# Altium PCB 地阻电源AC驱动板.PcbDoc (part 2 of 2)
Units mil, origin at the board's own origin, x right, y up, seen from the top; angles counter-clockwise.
Board outline 3149.61 x 5118.11 mil, 2 copper layers (Top Layer, Bottom Layer); 154 components, 62 nets, 426 pads, 73 vias.
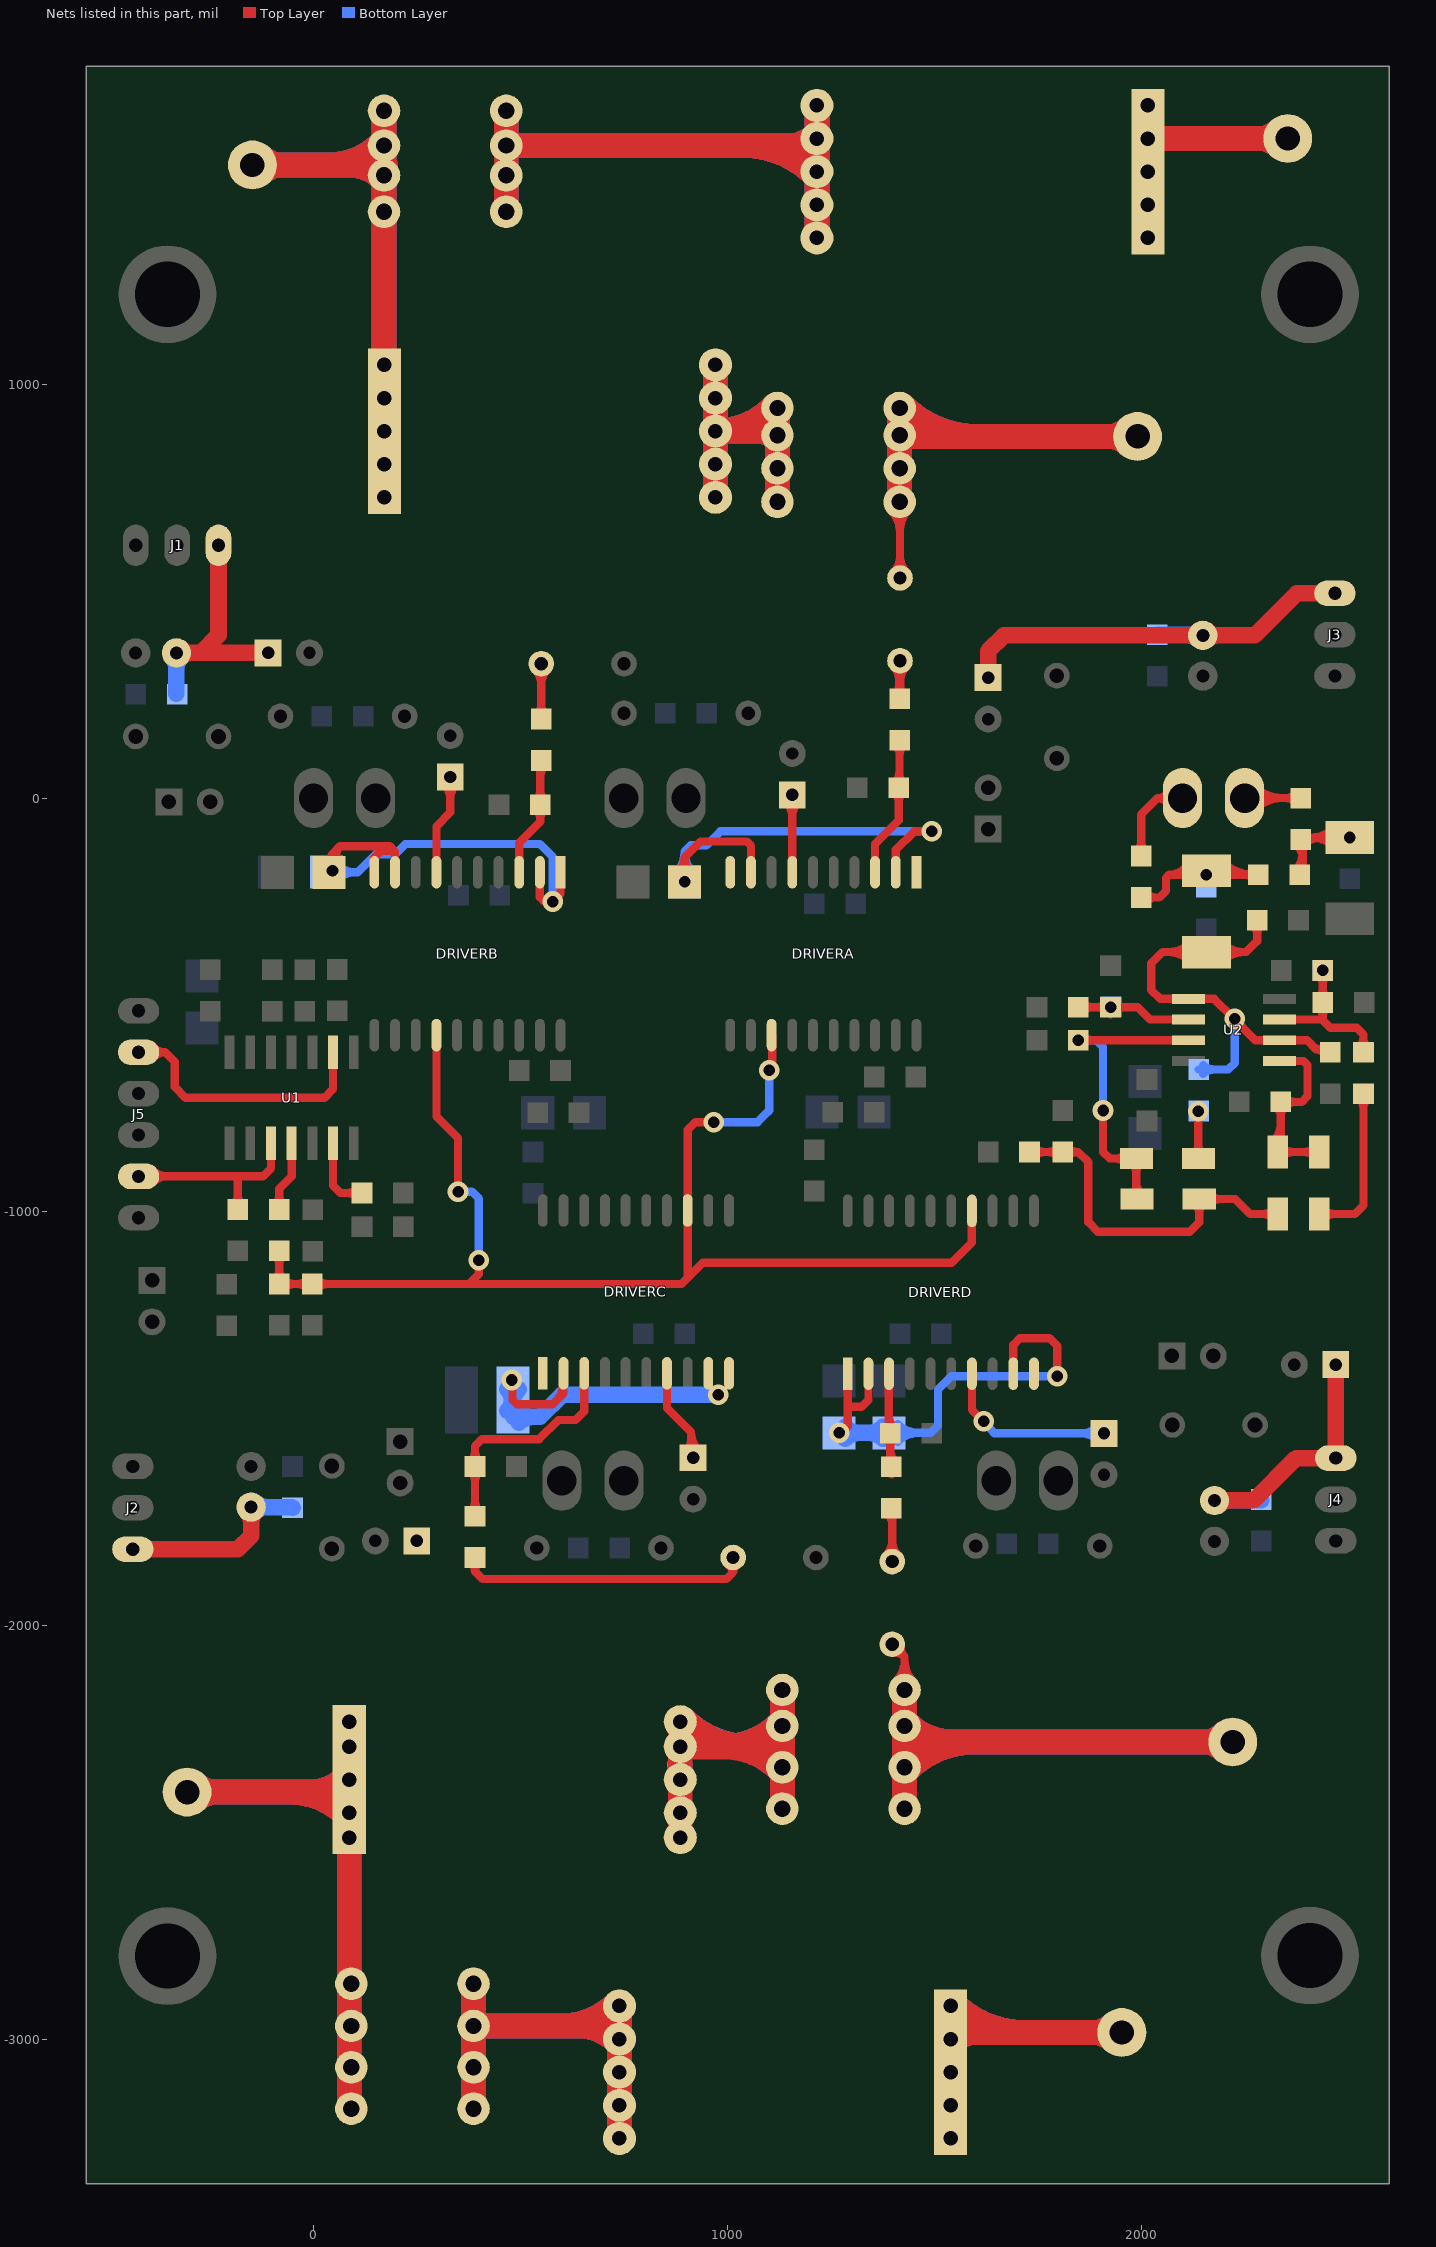
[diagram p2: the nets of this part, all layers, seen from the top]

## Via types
v1: diameter 50, hole 28, Top Layer to Bottom Layer, 54 vias
v2: diameter 50, hole 27.99, Top Layer to Bottom Layer, 19 vias

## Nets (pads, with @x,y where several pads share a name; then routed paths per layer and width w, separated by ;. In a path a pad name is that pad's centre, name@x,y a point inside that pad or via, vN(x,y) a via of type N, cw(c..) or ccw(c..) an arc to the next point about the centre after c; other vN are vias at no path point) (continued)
IPM2: J5.2 R50.1 U1.3 | length 565
  Top Layer w20: J5.2@-389.06,-929.02 cw(c-353.21,-964.87) -353.21,-914.17 cw(c-353.21,-863.47) J5.2@-389.06,-899.32 ; J5.2@-382.91,-914.17 -122.28,-914.17 -102.91,-894.8 U1.3@-102.91,-834.17 ; R50.1@-193.52,-983.57 ccw(c-219.13,-957.96) -182.91,-957.96 ccw(c-146.7,-957.96) R50.1@-172.31,-983.57 ; R50.1@-182.91,-994.17 -182.91,-914.36
IPM2*: C47.1 DRIVERA.13 DRIVERB.14 DRIVERC.13 DRIVERD.14 R52.2 R56.2 | length 3584.5
  Top Layer w20: C47.1@-93.52,-1163.57 ccw(c-119.13,-1137.96) -82.91,-1137.96 ccw(c-46.7,-1137.96) -72.31,-1163.57 ccw(c-46.7,-1137.96) -46.7,-1174.17 ccw(c-46.7,-1210.39) C47.1@-72.31,-1184.78 ; R52.2@-93.52,-1104.78 cw(c-119.13,-1130.39) -82.91,-1130.39 cw(c-46.7,-1130.39) R52.2@-72.31,-1104.78 ; R52.2@-82.91,-1094.17 C47.1@-82.91,-1174.17 R56.2@-2.91,-1174.17 889.26,-1174.17 904.09,-1159.35 ; R56.2@-13.52,-1184.78 ccw(c-39.13,-1210.39) -39.13,-1174.17 ccw(c-39.13,-1137.96) R56.2@-13.52,-1163.57 ; R56.2@7.69,-1184.78 cw(c33.3,-1210.39) 33.3,-1174.17 cw(c33.3,-1137.96) R56.2@7.69,-1163.57 ; DRIVERB.14@296.94,-572.85 296.94,-769.67 349.28,-822.01 v2(349.28,-951.13) ; 375.28,-1174.01 399.28,-1150.01 v1(399.28,-1117.2) ; 940.28,-1123.16 904.09,-1159.35 ; 940.28,-1123.11 1541.72,-1123.11 1590.94,-1073.9 DRIVERD.14@1590.94,-997.46 ; v2(967.28,-783.16) 923.28,-783.16 904.09,-802.35 DRIVERC.13@904.09,-996.47 904.09,-1159.35 ; v2(1101.28,-658.01) 1108.28,-651.01 DRIVERA.13@1108.28,-574.2
  Bottom Layer w20: v2(349.28,-951.13) 382.4,-951.13 399.28,-968.01 v1(399.28,-1117.2) ; v2(967.28,-783.16) 1073.13,-783.16 1099.78,-756.51 ; 1101.28,-755.01 v2(1101.28,-658.01)
NetC1_2: C1.2 C2.2 C3.2 C4.2 R3.2 R4.2 R5.2 R6.2 R7.2 | length 2451.3
  Top Layer w60: C4.2@386.55,-3167.16 C3.2@386.55,-3067.16 C1.2@386.55,-2967.16 ; C2.2@386.55,-2865.16 C1.2@386.55,-2967.16 ; 598.89,-2967.16 ccw(c598.89,-2778.62) R5.2@732.2,-2911.94 ; 638.24,-2967.16 cw(c638.24,-3100.04) R4.2@732.2,-3006.08 ; R4.2@737.43,-2967.16 C1.2@386.55,-2967.16 ; R6.2@739.28,-3239.01 R3.2@739.28,-3159.01 R7.2@739.28,-3079.01 R4.2@739.28,-2999.01 R5.2@739.28,-2919.01
  Bottom Layer w60: C4.2@386.55,-3167.16 C3.2@386.55,-3067.16 C1.2@386.55,-2967.16 ; C2.2@386.55,-2865.16 C1.2@386.55,-2967.16 ; 598.89,-2967.16 ccw(c598.89,-2778.62) R5.2@732.2,-2911.94 ; 638.24,-2967.16 cw(c638.24,-3100.04) R4.2@732.2,-3006.08 ; R4.2@738.13,-2967.16 C1.2@386.55,-2967.16 ; R6.2@739.28,-3239.01 R3.2@739.28,-3159.01 R7.2@739.28,-3079.01 R4.2@739.28,-2999.01 R5.2@739.28,-2919.01
NetC8_2: C8.2 C9.2 C10.2 C11.2 R15.2 R16.2 R17.2 R18.2 R19.2 | length 3114.5
  Top Layer w60: C11.2@465.55,1416.84 C10.2@465.55,1504.84 C9.2@465.55,1576.84 ; C8.2@465.55,1660.84 C9.2@465.55,1576.84 ; 1040.04,1576.84 cw(c1040.04,1337.61) R19.2@1209.2,1506.77 ; 1151.09,1576.84 ccw(c1151.09,1659.03) R18.2@1209.2,1600.91 ; R18.2@1213.43,1576.84 C9.2@465.55,1576.84 ; R17.2@1216.28,1353.84 R16.2@1216.28,1433.84 R19.2@1216.28,1513.84 R18.2@1216.28,1593.84 R15.2@1216.28,1673.84
  Bottom Layer w60: C11.2@465.55,1416.84 C10.2@465.55,1504.84 C9.2@465.55,1576.84 ; C8.2@465.55,1660.84 C9.2@465.55,1576.84 ; 1040.04,1576.84 cw(c1040.04,1337.61) R19.2@1209.2,1506.77 ; 1151.09,1576.84 ccw(c1151.09,1659.03) R18.2@1209.2,1600.91 ; R18.2@1199.28,1576.84 C9.2@465.55,1576.84 ; R17.2@1216.28,1353.84 R16.2@1216.28,1433.84 R19.2@1216.28,1513.84 R18.2@1216.28,1593.84 R15.2@1216.28,1673.84
NetC16_1: C16.1 DRIVERB.3 R13.2 | length 459.4
  Top Layer w20: DRIVERB.3@496.94,-179.15 496.94,-108.57 548.7,-56.81 ; C16.1@537.48,-26.78 cw(c511.87,-52.39) 548.09,-52.39 cw(c584.3,-52.39) C16.1@558.69,-26.78 ; C16.1@537.48,-5.57 ccw(c511.87,20.04) 548.09,20.04 ccw(c584.3,20.04) C16.1@558.69,-5.57 ; R13.2@539.67,80.39 cw(c519.35,60.06) 548.09,60.06 ; 548.09,-56.2 C16.1@548.09,-16.17 R13.2@548.09,88.8 ; 548.09,49.49 cw(c591.77,49.49) R13.2@560.88,80.39
NetC18_1: C18.1 DRIVERC.3 R14.2 | length 730.1
  Top Layer w20: R14.2@379.67,-1724.55 ccw(c354.06,-1698.94) 390.28,-1698.94 ccw(c426.49,-1698.94) R14.2@400.88,-1724.55 ; C18.1@379.67,-1625.76 cw(c354.06,-1651.37) 390.28,-1651.37 cw(c426.49,-1651.37) C18.1@400.88,-1625.76 ; C18.1@379.67,-1604.55 ccw(c354.06,-1578.94) 390.28,-1578.94 ccw(c426.49,-1578.94) C18.1@400.88,-1604.55 ; R14.2@390.28,-1735.16 C18.1@390.28,-1615.16 390.28,-1566.16 407.28,-1549.16 545.28,-1549.16 591.65,-1502.78 633.28,-1502.78 654.09,-1481.97 DRIVERC.3@654.09,-1390.17
NetC20_2: C20.2 C21.2 C22.2 C23.2 R23.2 R24.2 R25.2 R26.2 R27.2 | length 2309.2
  Top Layer w60: R24.2@886.28,-2512.01 R23.2@886.28,-2452.01 R27.2@886.28,-2372.01 R26.2@886.28,-2292.01 R25.2@886.28,-2232.01 ; R26.2@892.28,-2293.01 1133,-2293.01 ; R25.2@893.35,-2224.94 ccw(c1057.69,-2060.6) 1057.69,-2293.01 ; 987.62,-2293.01 ccw(c987.62,-2096.77) C21.2@1126.37,-2235.53 ; 991.72,-2293.01 cw(c991.72,-2483.44) C22.2@1126.37,-2348.78 ; C20.2@1133,-2442.16 C22.2@1133,-2342.16 1133,-2293.01 ; C23.2@1133,-2155.16 C21.2@1133,-2242.16 1133,-2293.01
  Bottom Layer w60: R27.2@884.28,-2337.01 R27.2@886.28,-2337.01 ; R26.2@890.28,-2292.01 1133,-2292.01 ; R25.2@893.35,-2224.94 ccw(c1055.27,-2063.01) 1055.27,-2292.01 ; 989.31,-2292.01 cw(c989.31,-2485.85) C22.2@1126.37,-2348.78 ; 990.03,-2292.01 ccw(c990.03,-2099.19) C21.2@1126.37,-2235.53 ; C20.2@1133,-2442.16 C22.2@1133,-2342.16 1133,-2292.01 ; C23.2@1133,-2155.16 C21.2@1133,-2242.16 1133,-2292.01
NetC26_2: C26.2 C27.2 C28.2 C29.2 R34.2 R35.2 R36.2 R37.2 R38.2 | length 1792.5
  Top Layer w60: R37.2@971.28,726.84 R36.2@971.28,806.84 R35.2@971.28,886.84 ; R38.2@971.28,1046.84 R34.2@971.28,966.84 R35.2@971.28,886.84 ; 1074.24,886.84 cw(c1074.24,830.08) C28.2@1114.37,870.22 ; C29.2@1114.13,949.21 cw(c971.28,1081.6) R35.2@971.28,886.84 ; C28.2@1120.15,886.84 R35.2@971.28,886.84 ; C26.2@1121,715.84 C27.2@1121,796.84 C28.2@1121,876.84 C29.2@1121,942.84
  Bottom Layer w60: R37.2@971.28,726.84 R36.2@971.28,806.84 R35.2@971.28,886.84 ; R38.2@971.28,1046.84 R34.2@971.28,966.84 R35.2@971.28,886.84 ; 1074.24,886.84 cw(c1074.24,830.08) C28.2@1114.37,870.22 ; C28.2@1111,886.84 R35.2@971.28,886.84 ; C29.2@1114.13,949.21 cw(c971.28,1081.6) R35.2@971.28,886.84 ; C26.2@1121,715.84 C27.2@1121,796.84 C28.2@1121,876.84 C29.2@1121,942.84
NetC35_1: C35.1 DRIVERA.3 R33.2 | length 513.9
  Top Layer w20: DRIVERA.3@1356.94,-179.16 1356.94,-111.13 1413.94,-54.13 C35.1@1413.94,24.84 ; C35.1@1403.33,14.24 cw(c1377.72,-11.37) 1413.94,-11.37 cw(c1450.15,-11.37) C35.1@1424.54,14.24 ; C35.1@1403.33,35.45 ccw(c1372.08,66.7) 1416.28,66.7 ; R33.2@1405.67,129.24 cw(c1380.06,103.63) 1416.28,103.63 cw(c1452.49,103.63) R33.2@1426.88,129.24 ; C35.1@1416.28,28.25 R33.2@1416.28,139.84 ; 1416.28,55.41 ccw(c1444.5,55.41) C35.1@1424.54,35.45
  Top Layer w23: C35.1@1413.94,24.84 C35.1@1416.81,27.72
NetC36_1: C36.1 DRIVERD.3 R32.2 | length 398.4
  Top Layer w20: C36.1@1383.33,-1545.76 cw(c1357.72,-1571.37) 1393.94,-1571.37 cw(c1430.15,-1571.37) C36.1@1404.54,-1545.76 ; C36.1@1383.33,-1524.55 ccw(c1366.56,-1507.78) 1390.28,-1507.78 ; R32.2@1385.67,-1605.55 ccw(c1365.71,-1585.59) 1393.94,-1585.59 ; C36.1@1390.28,-1536.16 C36.1@1390.28,-1535.16 ; 1390.28,-1490.1 ccw(c1438.99,-1490.1) C36.1@1404.54,-1524.55 ; DRIVERD.3@1390.28,-1395.16 C36.1@1390.28,-1535.16 ; R32.2@1393.94,-1631.02 R32.2@1397.09,-1634.17 ; R32.2@1393.94,-1613.82 C36.1@1393.94,-1535.16 C36.1@1390.28,-1535.16 ; 1393.94,-1574.3 ccw(c1438.14,-1574.3) R32.2@1406.88,-1605.55
NetC39_2: C39.2 C43.1 L1.1 R41.2 | length 676.6
  Top Layer w20: R41.2@2000,-240 2044,-240 2060,-224 2060,-193 2067.84,-185.16 ; R41.2@2010.61,-250.61 cw(c2036.21,-276.21) 2036.21,-240 cw(c2036.21,-203.79) R41.2@2010.61,-229.39 ; 2090.16,-185.16 cw(c2090.16,-223.24) L1.1@2117.08,-196.31 ; L1.1@2112.88,-160.08 cw(c2067.85,-132.18) 2067.85,-185.16 ; L1.1@2183.85,-168.92 ccw(c2223.05,-129.71) 2223.05,-185.16 ; L1.1@2197.99,-196.31 cw(c2224.92,-223.24) 2224.92,-185.16 ; L1.1@2197.99,-154.78 ccw(c2271.34,-81.43) C43.1@2271.34,-185.16 ; C43.1@2272.67,-195.76 ccw(c2247.06,-221.37) 2247.06,-185.16 ccw(c2247.06,-148.94) C43.1@2272.67,-174.55 ; C43.1@2283.28,-185.16 v1(2157.54,-185.16) 2067.84,-185.16
NetC40_1: C40.1 L1.2 R39.2 R55.1 U2.2 U2.5 | length 1473.5
  Top Layer w20: 2066.01,-372.01 cw(c2066.01,-444.23) L1.2@2117.08,-393.16 ; 2067.88,-372.01 ccw(c2067.88,-302.42) L1.2@2117.08,-351.63 ; L1.2@2197.99,-393.16 cw(c2249.06,-444.23) 2249.06,-372.01 ; L1.2@2197.99,-351.63 ccw(c2247.2,-302.42) 2247.2,-372.01 ; 2247.52,-557.16 2275.51,-585.16 U2.2@2333.94,-585.16 2400.51,-585.16 2422.72,-607.36 ; 2247.52,-556.18 2225.31,-533.97 2176.5,-485.16 U2.5@2113.94,-485.16 2046.28,-485.16 2024.28,-463.16 2024.28,-399.16 2051.43,-372.01 L1.2@2157.15,-372.01 ; C40.1@2269.67,-305.61 cw(c2244.06,-331.22) 2280.28,-331.22 cw(c2316.49,-331.22) C40.1@2290.88,-305.61 ; C40.1@2280.28,-295.01 2280.28,-345.62 2253.89,-372.01 L1.2@2157.54,-372.01 ; 2414.29,-598.94 ccw(c2433.14,-580.09) R39.2@2448.46,-601.9 ; R39.2@2443.51,-620.56 ccw(c2422.72,-630.35) 2422.72,-607.36 ; R39.2@2444.37,-607.36 2422.72,-607.36 ; L1.2@2157.15,-372.01 L1.2@2157.54,-372.01 ; L1.2@2157.15,-372.01 L1.2@2157.54,-372.39 L1.2@2157.54,-372.01
  Bottom Layer w20: R55.1@2139.28,-656.01 2210.28,-656.01 2226.28,-640.01 v1(2226.28,-533.01) ; R55.1@2149.88,-666.61 cw(c2175.49,-692.22) 2175.49,-656.01 cw(c2175.49,-619.79) R55.1@2149.88,-645.4
NetC42_1: C42.1 R43.2 R47.1 U2.6 | length 467.8
  Top Layer w20: R43.2@1848.09,-505.17 v2(1926.09,-505.17) ; R43.2@1858.69,-515.78 cw(c1884.3,-541.39) 1884.3,-505.17 cw(c1884.3,-468.96) R43.2@1858.69,-494.57 ; R47.1@1915.48,-515.78 ccw(c1889.87,-541.39) 1889.87,-505.17 ccw(c1889.87,-468.96) R47.1@1915.48,-494.57 ; R47.1@1926.09,-522.11 v2(1926.09,-505.17) ; R47.1@1936.69,-515.78 cw(c1962.3,-541.39) 1962.3,-505.17 cw(c1962.3,-468.96) R47.1@1936.69,-494.57 ; U2.6@2112.6,-536.5 U2.6@2113.94,-535.16 2021.28,-535.16 1991.29,-505.17 v2(1926.09,-505.17)
NetC43_2: C43.2 C45.1 L2.1 R48.2 | length 438.1
  Top Layer w20: C43.2@2372.67,-174.55 ccw(c2330.16,-132.04) 2390.28,-132.04 ; R48.2@2374.83,-110.61 cw(c2337.53,-147.9) 2390.28,-147.9 ; C43.2@2390.28,-178.16 2390.28,-100 2390.28,-95.16 v2(2503.94,-95.16) ; R48.2@2396.04,-110.61 cw(c2433.34,-147.9) 2433.34,-95.16 ; L2.1@2463.48,-115.92 ccw(c2413.35,-166.06) 2413.35,-95.16 ccw(c2413.35,-24.25) L2.1@2463.48,-74.39
NetC46_1: C46.1 R49.1 R53.2 R54.2 U2.3 | length 606.8
  Top Layer w20: U2.3@2333.94,-535.16 2433.5,-535.16 ; R49.1@2428.17,-504.78 cw(c2402.57,-530.39) 2438.78,-530.39 cw(c2474.99,-530.39) R49.1@2449.39,-504.78 ; R49.1@2428.17,-483.57 ccw(c2402.57,-457.96) 2438.78,-457.96 ccw(c2474.99,-457.96) R49.1@2449.39,-483.57 ; R53.2@2428.17,-427.04 cw(c2402.57,-452.65) 2438.78,-452.65 cw(c2474.99,-452.65) R53.2@2449.39,-427.04 ; 2437.09,-535.16 2437.17,-535.16 ; R49.1@2437.09,-514.17 R49.1@2438.78,-512.48 ; v1(2438.78,-416.43) R49.1@2438.78,-494.17 R49.1@2438.78,-512.48 ; R54.2@2526.48,-603.57 ccw(c2500.87,-577.96) 2537.09,-577.96 ccw(c2573.3,-577.96) R54.2@2547.69,-603.57 ; R54.2@2537.09,-614.17 2537.09,-571.14 2521.14,-555.2 2457.2,-555.2 2437.17,-535.16 ; 2437.17,-535.16 2438.78,-533.54 R49.1@2438.78,-512.48
NetD5_1: D5.1 R13.1 | length 276
  Top Layer w20: D5.1@535.43,309.99 cw(c499.58,274.14) 550.28,274.14 cw(c600.97,274.14) D5.1@565.13,309.99 ; R13.1@539.67,201.6 ccw(c514.06,227.21) 550.28,227.21 ccw(c586.49,227.21) R13.1@560.88,201.6 ; D5.1@546.28,320.84 D5.1@550.28,324.84 R13.1@550.28,190.99
NetD6_1: D6.1 R14.1 | length 883
  Top Layer w20: R14.1@380.16,-1846.24 cw(c359.25,-1869.16) 390.28,-1869.16 ; R14.1@390.28,-1835.16 390.28,-1869.16 ; R14.1@400.39,-1846.24 ccw(c421.31,-1869.16) 390.28,-1869.16 ; D6.1@1001.87,-1852.34 cw(c987.73,-1872.47) 1012.33,-1872.47 ; D6.1@1003.22,-1853.22 cw(c993.74,-1869.21) 1012.33,-1869.21 cw(c1028.27,-1869.21) D6.1@1022.09,-1854.51 ; D6.1@1004.53,-1853.93 cw(c996.89,-1869.17) 1013.94,-1869.17 ; 1012.33,-1869.17 1012.33,-1872.44 ; D6.1@1012.33,-1836.77 D6.1@1013.94,-1835.16 1013.94,-1869.17 ; D6.1@1023.35,-1853.93 ccw(c1030.98,-1869.17) 1013.94,-1869.17 ; D6.1@1023.66,-1853.77 ccw(c1033.43,-1872.47) 1012.33,-1872.47 ; 390.28,-1869.16 408.28,-1887.16 997.61,-1887.16 1012.33,-1872.44
NetD11_1: D11.1 R32.1 | length 263.4
  Top Layer w20: D11.1@1383.43,-1830.16 ccw(c1347.58,-1794.31) 1398.28,-1794.31 ccw(c1448.97,-1794.31) D11.1@1413.13,-1830.16 ; R32.1@1385.67,-1726.76 cw(c1355.23,-1757.2) 1398.28,-1757.2 ; D11.1@1398.28,-1845.01 R32.1@1398.28,-1718.16 ; 1398.28,-1747.54 cw(c1427.66,-1747.54) R32.1@1406.88,-1726.76
NetD12_1: D12.1 R33.1 | length 217.6
  Top Layer w23: D12.1@1403.49,318.05 cw(c1372.61,287.18) 1416.28,287.18 ; R33.1@1406.73,249.39 ccw(c1383.68,272.43) 1416.28,272.43 ccw(c1448.87,272.43) R33.1@1425.82,249.39 ; R33.1@1416.28,239.84 1416.28,330.84 D12.1@1417.28,331.84 ; 1416.28,282.35 cw(c1466.77,282.35) D12.1@1431.06,318.05
NetD13_1: D13.1 R54.1 | length 499.5
  Top Layer w20: D13.1@2430.28,-1005.16 2516.43,-1005.16 2537.09,-984.5 R54.1@2537.09,-714.17 ; D13.1@2440.88,-1015.76 cw(c2466.49,-1041.37) 2466.49,-1005.16 cw(c2466.49,-968.94) D13.1@2440.88,-994.55 ; R54.1@2526.48,-724.78 cw(c2500.87,-750.39) 2537.09,-750.39 cw(c2573.3,-750.39) R54.1@2547.69,-724.78
NetD13_2: D13.2 D14.2 R45.1 U2.1 | length 709.1
  Top Layer w20: D14.2@2319.67,-829.55 ccw(c2277.62,-787.5) 2337.09,-787.5 ; R45.1@2326.48,-744.78 cw(c2300.87,-770.39) 2337.09,-770.39 cw(c2373.3,-770.39) 2347.69,-744.78 cw(c2373.3,-770.39) 2373.3,-734.17 cw(c2373.3,-697.96) R45.1@2347.69,-723.57 ; D14.2@2330.28,-855.16 D14.2@2340.28,-855.16 ; U2.1@2333.94,-635.16 2392.44,-635.16 2402.09,-644.8 2402.09,-720.38 2388.29,-734.17 R45.1@2337.09,-734.17 D14.2@2337.09,-848.35 ; D14.2@2340.28,-857.16 D14.2@2340.28,-855.16 ; D14.2@2340.88,-865.76 cw(c2366.49,-891.37) 2366.49,-855.16 cw(c2366.49,-818.94) D14.2@2340.88,-844.55 ; D13.2@2419.67,-865.76 ccw(c2394.06,-891.37) 2394.06,-855.16 ccw(c2394.06,-818.94) D13.2@2419.67,-844.55 ; D13.2@2430.09,-844.35 D13.2@2430.28,-844.16 ; D13.2@2430.28,-855.16 D14.2@2340.28,-855.16
NetD14_1: D14.1 D15.1 R51.2 R57.1 | length 1186.8
  Top Layer w20: R57.1@1730.28,-855.16 R51.2@1810.28,-855.16 1847.43,-855.16 1872.28,-880.01 1872.28,-1025.01 1895.43,-1048.16 2117.28,-1048.16 2140.28,-1025.16 D15.1@2140.28,-969.01 2227.28,-969.01 2263.43,-1005.16 D14.1@2330.28,-1005.16 ; R57.1@1740.88,-865.76 cw(c1766.49,-891.37) 1766.49,-855.16 cw(c1766.49,-818.94) R57.1@1740.88,-844.55 ; R51.2@1799.67,-865.76 ccw(c1774.06,-891.37) 1774.06,-855.16 ccw(c1774.06,-818.94) R51.2@1799.67,-844.55 ; R51.2@1820.88,-865.76 cw(c1846.49,-891.37) 1846.49,-855.16 cw(c1846.49,-818.94) R51.2@1820.88,-844.55 ; D15.1@2129.67,-979.61 cw(c2104.06,-1005.22) 2140.28,-1005.22 cw(c2176.49,-1005.22) D15.1@2150.88,-979.61 ; D15.1@2165.88,-979.61 cw(c2191.49,-1005.22) 2191.49,-969.01 cw(c2191.49,-932.79) D15.1@2165.88,-958.4 ; D14.1@2319.67,-1015.76 ccw(c2294.06,-1041.37) 2294.06,-1005.16 ccw(c2294.06,-968.94) D14.1@2319.67,-994.55
NetD15_2: D15.2 D16.2 R40.1 U2.7 | length 996.3
  Top Layer w20: v2(1848.09,-585.17) U2.7@2113.94,-585.16 ; R40.1@1858.69,-595.78 cw(c1884.34,-621.42) 1884.34,-585.16 ; R40.1@1858.69,-574.57 ccw(c1884.26,-549) 1884.26,-585.16 ; v2(1907.95,-755) 1907.95,-854.98 1924.13,-871.16 D16.2@1988.28,-871.16 D15.2@1988.28,-967.01 ; D16.2@1962.67,-881.76 ccw(c1937.06,-907.37) 1937.06,-871.16 ccw(c1937.06,-834.94) D16.2@1962.67,-860.55 ; D16.2@1977.67,-881.76 cw(c1952.06,-907.37) 1988.28,-907.37 cw(c2024.49,-907.37) D16.2@1998.88,-881.76 ; D15.2@1979.67,-958.4 ccw(c1958.89,-937.62) 1988.28,-937.62 ; 1988.28,-927.97 ccw(c2031.32,-927.97) D15.2@2000.88,-958.4
  Bottom Layer w20: v2(1848.09,-585.17) 1891.44,-585.17 1907.95,-601.68 v2(1907.95,-755)
NetD16_1: D16.1 R55.2 | length 166
  Top Layer w20: D16.1@2127.67,-860.55 ccw(c2102.06,-834.94) 2138.28,-834.94 ccw(c2174.49,-834.94) D16.1@2148.88,-860.55 ; D16.1@2138.28,-866.16 v2(2138.28,-757.01)
NetDRIVERA_7: DRIVERA.7 R30.1 | length 282.7
  Top Layer w20: R30.1@1141.03,-8.07 cw(c1102.62,-46.48) 1156.94,-46.48 cw(c1211.26,-46.48) R30.1@1172.85,-8.07 ; DRIVERA.7@1156.94,-179.16 R30.1@1156.94,7.84 R30.1@1156.94,18.18
NetDRIVERB_7: DRIVERB.7 R8.1 | length 329.3
  Top Layer w20: DRIVERB.7@296.94,-179.15 296.94,-68.35 330.28,-35.01 R8.1@330.28,50.99 ; R8.1@314.37,35.08 cw(c275.96,-3.33) 330.28,-3.33 cw(c384.6,-3.33) R8.1@346.19,35.08
NetDRIVERC_7: DRIVERC.7 R9.1 | length 319.1
  Top Layer w20: DRIVERC.7@854.09,-1390.17 854.09,-1473.97 912.28,-1532.16 ; R9.1@901.18,-1578.26 ccw(c874.38,-1551.47) 912.28,-1551.47 ; R9.1@922.87,-1588.39 R9.1@917.09,-1594.17 912.28,-1589.36 912.28,-1532.16 ; R9.1@932.28,-1577.57 cw(c973.84,-1532.16) 912.28,-1532.16
NetDRIVERD_7: DRIVERD.7 R28.1 | length 524.9
  Top Layer w20: DRIVERD.7@1591.28,-1388.16 1591.28,-1391.16 1591.28,-1478.16 v1(1619.28,-1506.16) ; R28.1@1917.28,-1521.16 R28.1@1917.28,-1515.16
  Bottom Layer w20: v1(1619.28,-1506.16) 1645.28,-1535.16 R28.1@1910.28,-1535.16 ; R28.1@1894.37,-1551.07 ccw(c1855.96,-1589.48) 1855.96,-1535.16 ccw(c1855.96,-1480.84) R28.1@1894.37,-1519.25
NetR44_1: R44.1 U1.6 | length 236.5
  Top Layer w20: U1.6@47.09,-834.17 47.09,-936.46 64.8,-954.17 R44.1@117.09,-954.17 ; R44.1@106.48,-964.78 ccw(c80.87,-990.39) 80.87,-954.17 ccw(c80.87,-917.96) R44.1@106.48,-943.57
NetR52_1: R52.1 U1.4 | length 229.3
  Top Layer w20: R52.1@-93.52,-983.57 ccw(c-119.13,-957.96) -82.91,-957.96 ccw(c-46.7,-957.96) R52.1@-72.31,-983.57 ; R52.1@-82.91,-994.17 -82.91,-944.68 -52.91,-914.68 U1.4@-52.91,-834.17
NUM5: pad.0@1953.28,-2983.01 R3.1 R4.1 R5.1 R6.1 R7.1 | length 2135.6
  Top Layer w60: R6.1@1539.28,-3239.01 R3.1@1539.28,-3159.01 R7.1@1539.28,-3079.01 R4.1@1539.28,-2999.01 1539.28,-2975.01 1547.28,-2983.01 pad.0@1953.28,-2983.01 ; R4.1@1546.35,-3006.08 cw(c1602.05,-3061.78) 1602.05,-2983.01 ; R5.1@1546.35,-2911.94 ccw(c1717.93,-2740.36) 1717.93,-2983.01 ; pad.0@1932.73,-3003.55 ccw(c1883.13,-3053.15) 1883.13,-2983.01 ccw(c1883.13,-2912.86) pad.0@1932.73,-2962.46
  Bottom Layer w60: R6.1@1539.28,-3239.01 R3.1@1539.28,-3159.01 R7.1@1539.28,-3079.01 R4.1@1539.28,-2999.01 R5.1@1539.28,-2919.01 ; R4.1@1544.28,-2983.01 pad.0@1953.28,-2983.01 ; R4.1@1546.35,-3006.08 cw(c1602.05,-3061.78) 1602.05,-2983.01 ; R5.1@1546.35,-2911.94 ccw(c1717.93,-2740.36) 1717.93,-2983.01 ; pad.0@1932.73,-3003.55 ccw(c1883.13,-3053.15) 1883.13,-2983.01 ccw(c1883.13,-2912.86) pad.0@1932.73,-2962.46
NUM5A: pad.0@2354.28,1593.99 R15.1 R16.1 R17.1 R18.1 R19.1 | length 1536.1
  Top Layer w60: R17.1@2016.28,1353.84 R16.1@2016.28,1433.84 R19.1@2016.28,1513.84 R18.1@2016.28,1593.84 R15.1@2016.28,1673.84 ; R18.1@2016.43,1593.99 pad.0@2354.28,1593.99 ; pad.0@2333.73,1573.45 ccw(c2284.13,1523.85) 2284.13,1593.99 ccw(c2284.13,1664.14) pad.0@2333.73,1614.54
  Bottom Layer w60: R17.1@2016.28,1353.84 R16.1@2016.28,1433.84 R19.1@2016.28,1513.84 R18.1@2016.28,1593.84 R15.1@2016.28,1673.84 ; R18.1@2016.43,1593.99 pad.0@2354.28,1593.99 ; pad.0@2333.73,1573.45 ccw(c2284.13,1523.85) 2284.13,1593.99 ccw(c2284.13,1664.14) pad.0@2333.73,1614.54
NUM6: C20.1 C21.1 C22.1 C23.1 D11.2 pad.0@2221.28,-2281.01 | length 3271.3
  Top Layer w20: D11.2@1398.28,-2045.01 1428.28,-2075.01 ; D11.2@1401.08,-2065.82 cw(c1405.4,-2097.88) 1428.27,-2075.01 ; C23.1@1407.51,-2134.39 ccw(c1357.37,-2084.25) 1428.28,-2084.25 ccw(c1499.18,-2084.25) C23.1@1449.04,-2134.39 ; D11.2@1419.09,-2047.81 ccw(c1451.15,-2052.13) 1428.27,-2075.01 ; C23.1@1428.28,-2155.16 1428.28,-2075.01
  Top Layer w60: C20.1@1428.28,-2442.16 C22.1@1428.28,-2342.16 C21.1@1428.28,-2242.16 C23.1@1428.28,-2155.16 ; C22.1@1434.9,-2348.78 cw(c1598.16,-2512.05) 1598.16,-2281.16 ; C21.1@1434.9,-2235.53 ccw(c1545.05,-2125.38) 1545.05,-2281.16 ; 1445.28,-2281.16 2221.13,-2281.16 pad.0@2221.28,-2281.01 ; 2150.77,-2281.16 ccw(c2150.77,-2210.5) pad.0@2200.73,-2260.46 ; 2151.49,-2281.16 cw(c2151.49,-2350.79) pad.0@2200.73,-2301.55
  Bottom Layer w60: C20.1@1428.28,-2442.16 C22.1@1428.28,-2342.16 C21.1@1428.28,-2242.16 C23.1@1428.28,-2155.16 C23.1@1428.28,-2142.16 ; 1434.28,-2281.16 2221.13,-2281.16 pad.0@2221.28,-2281.01 ; C22.1@1434.9,-2348.78 cw(c1598.16,-2512.05) 1598.16,-2281.16 ; C21.1@1434.9,-2235.53 ccw(c1545.05,-2125.38) 1545.05,-2281.16 ; 2150.77,-2281.16 ccw(c2150.77,-2210.5) pad.0@2200.73,-2260.46 ; 2151.49,-2281.16 cw(c2151.49,-2350.79) pad.0@2200.73,-2301.55
NUM6A: C26.1 C27.1 C28.1 C29.1 D12.2 pad.1@1991.28,873.99 | length 2591.3
  Top Layer w20: C26.1@1395.51,695.08 cw(c1342.96,642.52) 1417.28,642.52 ; D12.2@1402.43,546.69 ccw(c1366.58,582.54) 1417.28,582.54 ccw(c1467.97,582.54) D12.2@1432.13,546.69 ; D12.2@1417.28,531.84 C26.1@1417.28,710.84 ; 1417.28,647.35 cw(c1484.77,647.35) C26.1@1437.04,695.08
  Top Layer w60: C26.1@1416.28,715.84 C27.1@1416.28,796.84 C28.1@1416.28,876.84 C29.1@1416.28,942.84 ; C28.1@1421.28,873.99 pad.1@1991.28,873.99 ; C29.1@1422.9,949.47 ccw(c1605.12,1131.68) 1605.12,873.99 ; pad.1@1970.73,853.45 ccw(c1921.13,803.85) 1921.13,873.99 ccw(c1921.13,944.14) pad.1@1970.73,894.54
  Bottom Layer w60: C26.1@1416.28,715.84 C27.1@1416.28,796.84 C28.1@1416.28,876.84 C29.1@1416.28,942.84 ; C28.1@1419.13,873.99 pad.1@1991.28,873.99 ; C29.1@1422.9,949.47 ccw(c1605.12,1131.68) 1605.12,873.99 ; pad.1@1970.73,853.45 ccw(c1921.13,803.85) 1921.13,873.99 ccw(c1921.13,944.14) pad.1@1970.73,894.54
NUM13: C8.1 C9.1 C10.1 C11.1 pad.3@-147.72,1529.99 R34.1 R35.1 R36.1 R37.1 R38.1 | length 3175.6
  Top Layer w60: pad.3@-147.72,1529.99 C10.1@170.28,1529.99 ; pad.3@-127.18,1509.45 cw(c-77.58,1459.85) -77.58,1529.99 cw(c-77.58,1600.14) pad.3@-127.18,1550.54 ; 34.55,1529.99 ccw(c34.55,1712.57) C9.1@163.65,1583.47 ; 86.94,1529.99 cw(c86.94,1421.51) C10.1@163.65,1498.22 ; R37.1@170.28,727.84 170.28,806.84 170.28,886.84 170.28,966.84 170.28,1046.84 C11.1@170.28,1416.84 C10.1@170.28,1504.84 C10.1@170.28,1529.99 ; C8.1@170.28,1660.84 C9.1@170.28,1576.84 C10.1@170.28,1529.99 ; C10.1@174.28,1529.99 C10.1@170.28,1529.99
  Bottom Layer w60: pad.3@-147.72,1529.99 C10.1@162.28,1529.99 ; pad.3@-127.18,1509.45 cw(c-77.58,1459.85) -77.58,1529.99 cw(c-77.58,1600.14) pad.3@-127.18,1550.54 ; 34.55,1529.99 ccw(c34.55,1712.57) C9.1@163.65,1583.47 ; 86.94,1529.99 cw(c86.94,1421.51) C10.1@163.65,1498.22 ; R37.1@170.28,727.84 170.28,806.84 170.28,886.84 170.28,966.84 170.28,1046.84 C11.1@170.28,1416.84 C10.1@170.28,1504.84 C9.1@170.28,1576.84 C8.1@170.28,1660.84
NUM14: C1.1 C2.1 C3.1 C4.1 pad.2@-305.72,-2402.16 R23.1 R24.1 R25.1 R26.1 R27.1 | length 3367.7
  Top Layer w60: pad.2@-305.72,-2402.16 R27.1@85.43,-2402.16 ; pad.2@-285.18,-2422.7 cw(c-235.58,-2472.3) -235.58,-2402.16 cw(c-235.58,-2332.01) pad.2@-285.18,-2381.61 ; -58.22,-2402.16 cw(c-58.22,-2596.5) R23.1@79.2,-2459.08 ; -10.65,-2402.16 ccw(c-10.65,-2275.08) R27.1@79.2,-2364.94 ; C4.1@86.28,-3162.01 86.28,-3067.16 86.28,-2967.16 86.28,-2865.16 R24.1@86.28,-2512.01 R23.1@86.28,-2452.01 R27.1@86.28,-2372.01 R26.1@86.28,-2292.01 R25.1@86.28,-2232.01
  Bottom Layer w60: pad.2@-305.72,-2402.16 R27.1@85.43,-2402.16 ; pad.2@-285.18,-2422.7 cw(c-235.58,-2472.3) -235.58,-2402.16 cw(c-235.58,-2332.01) pad.2@-285.18,-2381.61 ; -58.22,-2402.16 cw(c-58.22,-2596.5) R23.1@79.2,-2459.08 ; -10.65,-2402.16 ccw(c-10.65,-2275.08) R27.1@79.2,-2364.94 ; C4.1@86.28,-3162.16 86.28,-3067.16 86.28,-2967.16 86.28,-2865.16 R24.1@86.28,-2512.01 R23.1@86.28,-2452.01 R27.1@86.28,-2372.01 R26.1@86.28,-2292.01 R25.1@86.28,-2232.01
RST: J5.5 U1.9 | length 714.8
  Top Layer w20: J5.5@-422.91,-614.17 -358.86,-614.17 ; J5.5@-387.83,-627.68 cw(c-358.86,-652) -358.86,-614.17 ; J5.5@-387.83,-600.67 ccw(c-358.86,-576.34) -358.86,-614.17 ; U1.9@47.09,-614.17 47.09,-703.53 26.44,-724.17 -309.19,-724.17 -335.35,-698.01 -335.35,-637.68 -358.86,-614.17
T1: pad.8 R41.1 | length 339.5
  Top Layer w20: R41.1@1989.39,-129.39 ccw(c1963.79,-103.79) 2000,-103.79 ccw(c2036.21,-103.79) R41.1@2010.61,-129.39 ; R41.1@2000,-140 2000,-40 2040,0 ; pad.8@2066.62,-16.52 ccw(c2040,-29.7) 2040,0 ; pad.8@2066.62,16.53 cw(c2040,29.71) 2040,0 ; pad.8@2100,0 2040,0
T2: pad.0@2250,0 R48.1 | length 333.6
  Top Layer w20: pad.0@2250,0 R48.1@2385.43,0 ; pad.0@2276.34,-26.34 cw(c2339.92,-89.92) 2339.92,0 cw(c2339.91,89.91) pad.0@2276.34,26.34 ; R48.1@2374.83,-10.61 ccw(c2349.22,-36.21) 2349.22,0 ccw(c2349.22,36.21) R48.1@2374.83,10.61
VEE1: C19.1 DRIVERA.1 DRIVERA.2 DRIVERA.9 DRIVERA.10 E10.2 E17.2 E18.2 J3.1 R22.1 | length 2567.2
  Top Layer w20: E18.2@879.07,-178.03 ccw(c854.36,-143.75) 896.61,-143.75 ; v1(896.61,-202.36) 896.61,-143.75 ; E18.2@914.16,-178.03 cw(c938.87,-143.75) 896.61,-143.75 ; DRIVERA.9@1056.94,-179.16 1056.94,-115.09 1047,-105.16 935.2,-105.16 896.61,-143.75 ; DRIVERA.2@1406.94,-179.16 1406.94,-125 1451.78,-80.16 v1(1494.28,-80.16)
  Top Layer w40: R22.1@1630.28,290.99 1630.28,355.27 1668.28,393.27 E10.2@2148.94,393.27 2274.55,393.27 2376.28,494.99 J3.1@2468.28,494.99 ; 2111.68,393.27 cw(c2111.68,356.01) E10.2@2138.02,382.36 ; 2111.68,393.27 ccw(c2111.68,430.53) E10.2@2138.02,404.18 ; E10.2@2159.85,382.36 cw(c2186.2,356.01) 2186.2,393.27 ; E10.2@2159.85,404.18 ccw(c2186.2,430.53) 2186.2,393.27
  Bottom Layer w20: E17.2@875.4,-181.15 ccw(c824.19,-129.94) 896.61,-129.94 ccw(c969.04,-129.94) E17.2@917.83,-181.15 ; v1(896.61,-202.36) 896.61,-128.82 911.43,-114.01 949.28,-114.01 983.13,-80.16 v1(1494.28,-80.16)
  Bottom Layer w40: C19.1@2039.09,394.83 E10.2@2147.38,394.83 ; 2107.91,394.83 cw(c2107.91,352.25) E10.2@2138.02,382.36
VEE2: C6.1 DRIVERB.1 DRIVERB.2 DRIVERB.9 DRIVERB.10 E2.2 E6.2 E7.2 J1.1 R1.1 | length 2169.4
  Top Layer w20: E7.2@32.51,-150.4 ccw(c29.81,-134.73) 45.7,-134.73 ccw(c73.36,-134.73) E7.2@56.2,-156.43 ; E7.2@45.52,-173.85 cw(c70.52,-154.57) 48.19,-132.24 ; E7.2@52.28,-168.94 v1(45.7,-175.51) 45.7,-134.73 64.28,-116.16 ; E7.2@61.35,-161.64 cw(c88.68,-140.56) 64.28,-116.16 ; DRIVERB.10@146.94,-143.5 163.07,-127.37 195.4,-127.37 ; DRIVERB.10@148.75,-151.59 cw(c172.66,-151.59) 155.75,-134.68 ; DRIVERB.9@196.94,-179.15 196.94,-128.91 195.4,-127.37 ; DRIVERB.2@546.94,-179.15 546.94,-239.52 557.5,-250.08 v1(578.23,-250.08) 596.94,-231.37 DRIVERB.1@596.94,-179.15 ; 64.28,-116.16 184.19,-116.16 195.4,-127.37
  Top Layer w40: E2.2@-331.3,350.99 -272.72,350.99 ; E2.2@-320.39,340.08 cw(c-294.04,313.73) -294.04,350.99 cw(c-294.04,388.25) E2.2@-320.39,361.91 ; J1.1@-229.72,610.99 -229.72,393.99 -272.72,350.99 ; R1.1@-109.72,350.99 -272.72,350.99
  Bottom Layer w20: v1(45.7,-175.51) 45.7,-178.98 107.09,-178.98 150.28,-135.79 196.91,-135.79 221.87,-110.83 546.86,-110.83 578.23,-142.2 v1(578.23,-250.08) ; E6.2@52.12,-200.19 cw(c103.33,-251.4) 103.33,-178.98 cw(c103.33,-106.55) E6.2@52.12,-157.76
  Bottom Layer w40: E2.2@-342.21,340.08 cw(c-368.56,313.73) -331.3,313.73 cw(c-294.04,313.73) E2.2@-320.39,340.08 ; C6.1@-331.3,252.57 E2.2@-331.3,350.99
VEE3: C5.1 DRIVERC.1 DRIVERC.2 DRIVERC.9 DRIVERC.10 E1.2 E8.2 E9.2 J2.1 R2.1 | length 1693.1
  Top Layer w20: v1@481,-1405.16 481,-1406.16 481,-1454.92 491.24,-1465.16 577.84,-1465.16 604.09,-1438.91 DRIVERC.2@604.09,-1390.17 ; 588.43,-1454.57 ccw(c554.77,-1420.9) DRIVERC.2@602.28,-1417.85
  Top Layer w40: J2.1@-436.72,-1815.01 -182.72,-1815.01 -150.72,-1783.01 E1.2@-150.72,-1713.58 ; E1.2@-161.64,-1724.49 cw(c-187.98,-1750.84) -150.72,-1750.84 cw(c-113.47,-1750.84) E1.2@-139.81,-1724.49
  Bottom Layer w40: E1.2@-150.72,-1713.58 -52.3,-1713.58 C5.1@-50.72,-1715.16 ; E1.2@-139.81,-1724.49 cw(c-113.47,-1750.84) -113.47,-1713.58 ; E1.2@-139.81,-1702.67 ccw(c-113.47,-1676.32) -113.47,-1713.58 ; E8.2@467.94,-1428.31 cw(c440.59,-1455.67) E9.2@479.28,-1455.67 ; E9.2@468.14,-1481.02 ccw(c441.26,-1454.13) E8.2@479.28,-1454.13 ; E9.2@479.28,-1469.24 cw(c537.16,-1469.24) E8.2@496.23,-1428.31 ; E8.2@479.28,-1439.61 ccw(c537.83,-1439.61) 496.43,-1481.02 ccw(c530.57,-1446.87) 530.57,-1495.16 ccw(c530.57,-1543.44) E9.2@496.43,-1509.3 ; v1(479.28,-1406.16) 479.28,-1414.17 479.28,-1471.16 E9.2@492.78,-1484.66 ; E9.2@482.28,-1495.16 547.28,-1495.16 600.28,-1442.16 v1(978.28,-1442.16)
VEE4: C24.2 DRIVERD.1 DRIVERD.2 DRIVERD.9 DRIVERD.10 E11.2 E15.2 E16.2 J4.1 R29.1 | length 2165.5
  Top Layer w20: v1@1290.28,-1520.16 1290.94,-1519.5 1290.94,-1471.01 ; DRIVERD.1@1290.94,-1391.16 1290.94,-1471.01 ; DRIVERD.2@1340.94,-1391.16 1340.94,-1454.35 1324.28,-1471.01 1290.94,-1471.01 ; DRIVERD.9@1690.94,-1391.16 1690.94,-1321.15 1706.93,-1305.16 1778,-1305.16 1797.28,-1324.43 v1(1797.28,-1397.16)
  Top Layer w40: E11.2@2178.13,-1696.73 2272.55,-1696.73 2374.28,-1595.01 J4.1@2470.28,-1595.01 R29.1@2470.28,-1369.01 ; E11.2@2188.19,-1708.5 cw(c2216.59,-1736.89) 2216.59,-1696.73
  Bottom Layer w20: v1(1270.28,-1534.01) 1282.43,-1534.01 E16.2@1293.28,-1523.16 ; E15.2@1390.28,-1534.01 1491.28,-1534.01 1509.28,-1516.01 1509.28,-1429.16 1541.28,-1397.16 v1(1797.28,-1397.16) ; E15.2@1411.49,-1555.22 cw(c1462.7,-1606.43) 1462.7,-1534.01 cw(c1462.7,-1461.58) E15.2@1411.49,-1512.79
  Bottom Layer w40: E16.2@1282.43,-1534.01 E15.2@1390.28,-1534.01 ; E16.2@1284.42,-1548.15 cw(c1318.56,-1582.29) 1318.56,-1534.01 cw(c1318.56,-1485.72) E16.2@1284.42,-1519.87 ; E15.2@1376.13,-1548.15 ccw(c1341.99,-1582.29) 1341.99,-1534.01 ccw(c1341.99,-1485.72) E15.2@1376.13,-1519.87 ; E11.2@2177.28,-1697.58 2178.13,-1696.73 E11.2@2190.28,-1696.73 ; E11.2@2188.19,-1708.5 cw(c2216.59,-1736.89) 2216.59,-1696.73 ; E11.2@2190.51,-1696.5 E11.2@2190.28,-1696.73 ; C24.2@2290.28,-1696.73 E11.2@2190.28,-1696.73
pads on no net: DRIVERA.5 DRIVERB.5 DRIVERC.5 DRIVERD.5 J1.2 J2.2 J3.2 J4.2 U1.1 U1.2 U1.10 U1.11

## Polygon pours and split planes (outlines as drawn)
VEE4 on Top Layer (hatched 90Degree grid 20 track 20, remove dead copper): 1124.48,-1227 1446.18,-1227 1446.18,-1411 1387.15,-1411 1387.15,-1646 1117.59,-1646 1117.59,-1225
VEE4 on Top Layer (hatched 90Degree grid 20 track 20, remove dead copper): 1548.28,-1225.01 1548.28,-1404.01 1640.94,-1404.01 1640.94,-1734.01 2585.28,-1734.01 2585.28,-1312.01 1859.28,-1312.01 1859.28,-1226.01 1546.28,-1226.01
VEE2 on Top Layer (hatched 90Degree grid 20 track 20, remove dead copper): 150,0 257.28,0 257.28,-264.84 -438.72,-264.84 -438.72,451.99 1.28,451.99 1.28,10.99 258.28,10.99 0,10.99 0,0 150,0
VEE3 on Top Layer (hatched 90Degree grid 20 track 20, remove dead copper): -220.85,-1808.42 448.48,-1808.42 448.48,-1597.57 565.86,-1597.57 761.27,-1405.6 791,-1443.85 791,-1206 750.59,-1206 750.59,-1210.03 541.04,-1210.03 260.29,-1468.66 -220.85,-1558.6
VEE1 on Top Layer (hatched 90Degree grid 20 track 20, remove dead copper): 781.92,-39.64 1194.19,-39.64 1194.19,-328.8 813.9,-328.8 813.9,-38.64
VEE3 on Top Layer (hatched 90Degree grid 20 track 20, remove dead copper): 846.28,-1224.01 1115.28,-1224.01 1115.28,-1584.01 889.28,-1584.01 889.28,-1344.01 830.28,-1344.01 830.28,-1228.01
VEE2 on Top Layer (hatched 90Degree grid 20 track 20, remove dead copper): 535,21 653,21 653,-334 398,-334 398,-139 538,-139 538,16
VEE1 on Top Layer (hatched 90Degree grid 20 track 20, remove dead copper): 1386.24,320.78 1759.19,320.78 1759.19,-8.77 1502.38,-281.22 1370.19,-281.22 1370.19,317.77
GND2 on Bottom Layer (hatched 90Degree grid 20 track 20, remove dead copper): 660.28,391.99 -551.72,391.99 -551.72,-171.01 -253.72,-321.01 652.28,-329.01 656.28,391.99
GND1 on Bottom Layer (hatched 90Degree grid 20 track 20, remove dead copper): 659.28,387.99 1925.28,387.99 1925.28,151.99 1454.28,-319.01 659.28,-319.01
GND4 on Bottom Layer (hatched 90Degree grid 20 track 20, remove dead copper): 1111.28,-1255.01 2598.28,-1255.01 2598.28,-1866.01 1560.28,-1866.01 1560.28,-1936.01 1106.28,-1936.01 1106.28,-1254.01
GND3 on Bottom Layer (hatched 90Degree grid 20 track 20, remove dead copper): 1113.28,-1224.01 1113.28,-1888.01 -90.72,-1888.01 -90.72,-1546.01 110.28,-1546.01 428.28,-1228.01 1111.28,-1228.01
GND on Bottom Layer (hatched 90Degree grid 20 track 20, remove dead copper): -551.72,-470.01 -231.72,-329.01 2050.28,-323.01 2046.28,-95.01 2601.28,-102.01 2598.28,-993.01 1848.28,-993.01 1849.28,-1229.01 -29.72,-1217.01 -28.72,-1316.01 -552.72,-1317.01 -549.72,-466.01

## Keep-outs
Keep-Out Layer:
  lines w7.87: -549.72,-3349.01 -549.72,1769.1 2599.88,1769.1 2599.88,-3349.01 -549.72,-3349.01
  lines w39.37: -345.61,-326.16 1611.28,-326.16 ; 198.28,-1225.01 1962.28,-1225.01 ; 656.26,-324.16 656.26,435.84 ; 1113.66,-1887.28 1113.66,-1237.28 ; 1113.66,-1840.01 1113.66,-1907.53 1146.13,-1940.01 1154.28,-1940.01 1172.8,-1940.53 1559.8,-1940.53 ; 1241.72,438.98 1582.28,437.99

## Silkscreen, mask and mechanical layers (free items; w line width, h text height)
Top Overlay:
  text "5" at 2480.28,1568.99 h60
  text "13" at -362.72,1494.99 h60
  text "6" at 2134.28,833.99 h60
  text "+" at -531.72,590.99 h40
  text "+" at 2458,190 h40
  text "+5V" at -305.72,-1015.01 h40 r270
  text "+" at -453,-1546 h40
  text "+" at 2458,-1912 h40
  text "6" at 2341.28,-2307.01 h60
  text "14" at -514.72,-2435.01 h60
  text "5" at 2076.28,-3020.01 h60
Top Solder:
  lines w60: -305.72,-2402.16 85.43,-2402.16 ; -147.72,1529.99 172.28,1529.99 ; 86.28,-3162.16 86.28,-2232.01 ; 170.28,727.84 170.28,1660.84 ; 386.55,-3167.16 386.55,-2865.16 ; 386.55,-2967.16 738.43,-2967.16 ; 465.55,1416.84 465.55,1660.84 ; 465.55,1576.84 1216.43,1576.84 ; 739.28,-3239.01 739.28,-2919.01 ; 886.28,-2512.01 886.28,-2232.01 ; 895.28,-2295.01 1135.28,-2295.01 ; 971.28,726.84 971.28,1046.84 ; 971.28,885.99 1128.28,885.99 ; 1121,715.84 1121,942.84 ; 1133,-2442.16 1133,-2155.16 ; 1216.28,1353.84 1216.28,1673.84 ; 1416.28,715.84 1416.28,942.84 ; 1423.28,873.99 1991.28,873.99 ; 1426.28,-2281.16 2221.13,-2281.16 2221.28,-2281.01 ; 1428.28,-2442.16 1428.28,-2142.16 ; 1539.28,-3239.01 1539.28,-2919.01 ; 1546.28,-2983.01 1953.28,-2983.01 ; 2016.28,1353.84 2016.28,1673.84 ; 2017.28,1593.99 2354.28,1593.99
Bottom Solder:
  lines w60: -305.72,-2402.16 85.43,-2402.16 ; -147.72,1529.99 171.28,1529.99 ; 86.28,-3162.16 86.28,-2232.01 ; 170.28,727.84 170.28,1660.84 ; 386.55,-3167.16 386.55,-2865.16 ; 386.55,-2967.01 739.28,-2967.01 ; 465.55,1416.84 465.55,1660.84 ; 465.55,1576.84 1213.13,1576.84 ; 739.28,-3239.01 739.28,-2919.01 ; 886.28,-2512.01 886.28,-2232.01 ; 890.28,-2294.01 1133.28,-2294.01 ; 971.28,726.84 971.28,1046.84 ; 971.28,886.84 1125.13,886.84 ; 1121,715.84 1121,942.84 ; 1133,-2442.16 1133,-2155.16 ; 1216.28,1353.84 1216.28,1673.84 ; 1416.28,715.84 1416.28,942.84 ; 1422.28,873.99 1991.28,873.99 ; 1428.28,-2442.16 1428.28,-2155.16 ; 1436.28,-2281.01 2221.28,-2281.01 ; 1537.28,-2983.01 1953.28,-2983.01 ; 2016.43,1593.99 2354.28,1593.99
